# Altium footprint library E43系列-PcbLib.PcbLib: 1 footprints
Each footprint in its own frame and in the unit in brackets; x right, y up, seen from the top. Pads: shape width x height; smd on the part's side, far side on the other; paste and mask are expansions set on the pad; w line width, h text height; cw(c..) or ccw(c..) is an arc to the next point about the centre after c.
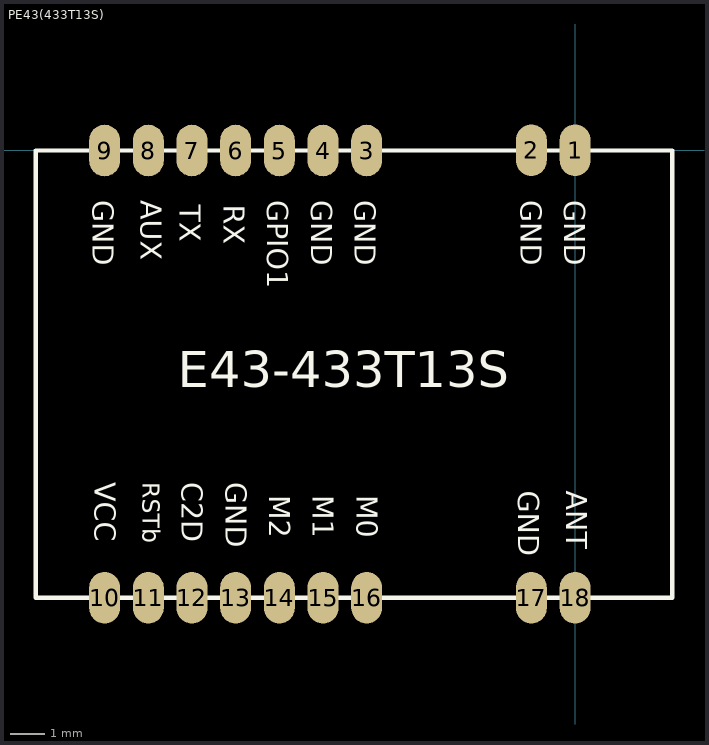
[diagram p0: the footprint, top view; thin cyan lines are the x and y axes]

## PE43(433T13S) [mm] "18.5mm*13.0mm*2.30mm-S"
pads (18):
  oval 0.9x1.5 smd: 1(0,0) 2(-1.273,0) 3(-6.058,-0.011) 4(-7.328,-0.011) 5(-8.598,-0.011) 6(-9.868,-0.011) 7(-11.138,-0.011) 8(-12.408,-0.011) 9(-13.678,-0.011) 10(-13.678,-13.011) 11(-12.408,-13.011) 12(-11.138,-13.011) 13(-9.868,-13.011) 14(-8.598,-13.011) 15(-7.328,-13.011) 16(-6.058,-13.011) 17(-1.273,-13.015) 18(0,-13.012)
Top Overlay:
  lines w0.127: -15.678,-13.011 2.822,-13.011 2.822,-0.011 -15.678,-0.011 -15.678,-13.011
  text "E43-433T13S" at -11.557,-7.239 h1.8
  text "ANT" at -0.254,-9.906 h0.6
  text "GND" at -14.027,-1.454 h0.6
  text "AUX" at -12.63,-1.454 h0.6
  text "TX" at -11.487,-1.581 h0.6
  text "GPIO1" at -8.947,-1.454 h0.6
  text "GND" at -7.677,-1.454 h0.6
  text "GND" at -6.407,-1.454 h0.6
  text "RX" at -10.217,-1.581 h0.6
  text "GND" at -10.16,-9.652 h0.6
  text "M0" at -6.35,-10.033 h0.6
  text "M1" at -7.62,-10.033 h0.6
  text "M2" at -8.89,-10.033 h0.6
  text "C2D" at -11.43,-9.652 h0.6
  text "RSTb" at -12.573,-9.652 h0.5
  text "VCC" at -13.97,-9.652 h0.6
  text "GND" at -1.581,-1.454 h0.6
  text "GND" at -0.311,-1.454 h0.6
  text "GND" at -1.651,-9.906 h0.6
